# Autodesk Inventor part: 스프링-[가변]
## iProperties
Created: 2014-12
Part Number: 스프링-[가변]
Document SubType Name: Modeling
Designer: elite
Density: 7.87 g/cm^3
Mass: 88.7116 g
Surface Area: 115.211 cm^2
Volume: 11.2721 cm^3
Material: 탄소강
Author: elite
